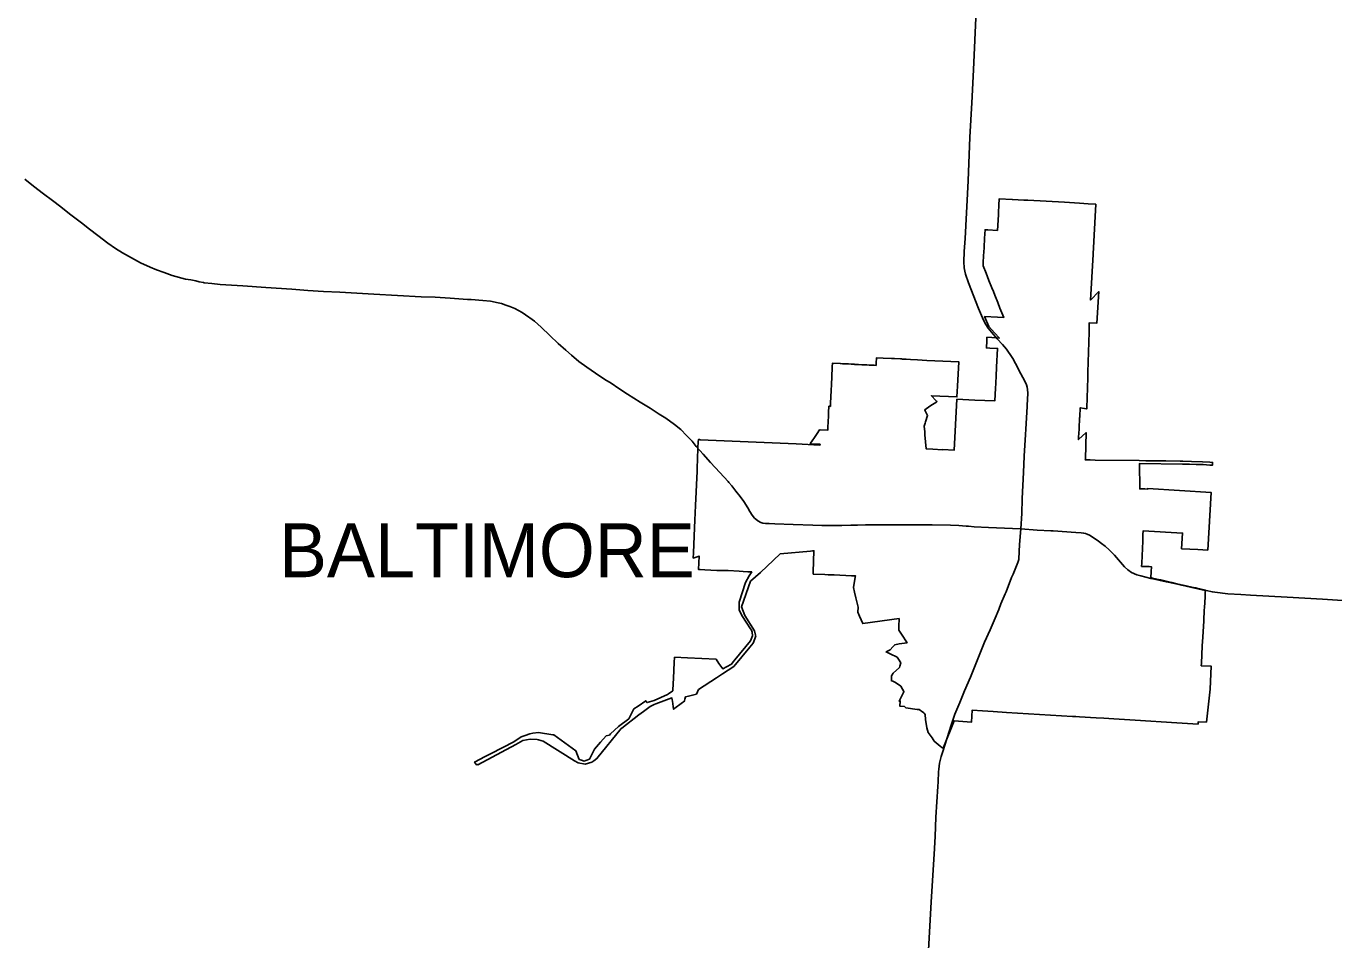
# Model space of a CAD drawing. Extents: x 1801177 to 2073177, y 551183 to 727183.
# Drawn here: x 1919316 to 1946535, y 663604 to 682611 of the extents above; entities that cross this region are included whole.
import ezdxf

# ---------------------------------------------------------------- set-up
doc = ezdxf.new("R2010")
doc.units = 0
for name, color, linetype in [('GM_X_Corporation', 7, 'Continuous'), ('GM_X_Corporation_Text', 7, 'Continuous'), ('GM_X_State_Route', 7, 'Continuous')]:
    doc.layers.add(name, color=color, linetype=linetype)

msp = doc.modelspace()

# ---------------------------------------------------------------- linework, layer by layer
at = {"layer": 'GM_X_Corporation'}
msp.add_lwpolyline([(1941583, 678909), (1941525, 677874), (1941524, 677860), (1941471, 676912), (1941643, 677090), (1941604, 676433), (1941444, 676441), (1941443, 676398), (1941439, 676247), (1941415, 675413), (1941413, 675297), (1941393, 674669), (1941392, 674649), (1941344, 674658), (1941255, 674674), (1941252, 674608), (1941249, 674554), (1941245, 674476), (1941244, 674460), (1941239, 674376), (1941237, 674328), (1941234, 674275), (1941233, 674262), (1941233, 674250), (1941232, 674236), (1941227, 674136), (1941227, 674130), (1941223, 674072), (1941221, 674027), (1941221, 674023), (1941220, 674011), (1941379, 674156), (1941363, 673613), (1941362, 673589), (1941465, 673587), (1941569, 673583), (1942485, 673573), (1942623, 673571), (1943036, 673566), (1943336, 673562), (1943390, 673562), (1943573, 673558), (1943798, 673549), (1943957, 673541), (1944012, 673537), (1944009, 673478), (1943954, 673481), (1943812, 673489), (1943670, 673495), (1943528, 673499), (1943386, 673502), (1942488, 673513), (1942496, 672986), (1942603, 672983), (1942659, 672981), (1942660, 672993), (1943983, 672909), (1943911, 671712), (1943705, 671722), (1943535, 671730), (1943366, 671739), (1943387, 672066), (1942565, 672112), (1942562, 672034), (1942559, 671968), (1942556, 671899), (1942537, 671440), (1942537, 671439), (1942534, 671373), (1942667, 671369), (1942689, 671368), (1942737, 671366), (1942733, 671263), (1942729, 671138), (1942741, 671135), (1942758, 671131), (1942762, 671130), (1942888, 671100), (1942932, 671090), (1943046, 671062), (1943103, 671049), (1943160, 671035), (1943318, 670998), (1943324, 670996), (1943326, 670996), (1943331, 670995), (1943348, 670990), (1943370, 670985), (1943399, 670979), (1943489, 670960), (1943643, 670928), (1943660, 670924), (1943680, 670919), (1943862, 670877), (1943860, 670836), (1943854, 670741), (1943841, 670509), (1943839, 670468), (1943826, 670238), (1943808, 669903), (1943797, 669718), (1943778, 669353), (1943775, 669307), (1943984, 669296), (1943958, 668816), (1943883, 668134), (1943712, 668142), (1943708, 668092), (1943269, 668119), (1942401, 668173), (1941956, 668200), (1941748, 668213), (1941590, 668223), (1941244, 668244), (1941167, 668249), (1941094, 668253), (1939722, 668336), (1939443, 668353), (1939222, 668369), (1939010, 668385), (1938994, 668135), (1938629, 668163), (1938400, 667594), (1938400, 667593), (1938373, 667603), (1938338, 667633), (1938338, 667633), (1938217, 667737), (1938171, 667803), (1938093, 667916), (1938063, 668011), (1938038, 668185), (1938026, 668291), (1938007, 668319), (1938002, 668326), (1937996, 668330), (1937983, 668339), (1937901, 668393), (1937879, 668396), (1937859, 668399), (1937629, 668430), (1937629, 668430), (1937615, 668442), (1937595, 668459), (1937504, 668463), (1937509, 668571), (1937499, 668572), (1937484, 668572), (1937528, 668654), (1937586, 668763), (1937583, 668769), (1937556, 668819), (1937552, 668829), (1937526, 668876), (1937524, 668880), (1937408, 668956), (1937370, 668975), (1937324, 668999), (1937325, 669012), (1937326, 669038), (1937329, 669098), (1937365, 669153), (1937491, 669270), (1937500, 669300), (1937523, 669369), (1937473, 669444), (1937445, 669486), (1937299, 669553), (1937284, 669560), (1937216, 669592), (1937298, 669640), (1937353, 669698), (1937395, 669741), (1937484, 669759), (1937651, 669784), (1937536, 669960), (1937480, 670047), (1937482, 670123), (1937486, 670287), (1936730, 670184), (1936730, 670184), (1936663, 670338), (1936627, 670420), (1936634, 670523), (1936614, 670608), (1936588, 670718), (1936557, 670839), (1936534, 670931), (1936575, 671146), (1936580, 671176), (1936492, 671179), (1936131, 671194), (1936008, 671199), (1935937, 671202), (1935700, 671211), (1935698, 671211), (1935699, 671261), (1935713, 671697), (1935683, 671694), (1935642, 671690), (1935009, 671632), (1934869, 671501), (1934603, 671249), (1934395, 671064), (1934209, 670531), (1934272, 670351), (1934475, 670035), (1934499, 669940), (1934502, 669928), (1934480, 669866), (1934447, 669775), (1934377, 669691), (1934046, 669291), (1933812, 669138), (1933807, 669135), (1933688, 669057), (1933314, 668811), (1933267, 668717), (1933267, 668717), (1933104, 668675), (1933040, 668659), (1933039, 668659), (1933027, 668614), (1933019, 668584), (1933019, 668569), (1932980, 668540), (1932792, 668402), (1932792, 668402), (1932768, 668568), (1932764, 668596), (1932757, 668638), (1932757, 668638), (1932423, 668516), (1932385, 668498), (1932306, 668459), (1932166, 668355), (1932071, 668284), (1931712, 668009), (1931700, 668000), (1931195, 667373), (1931130, 667327), (1931090, 667299), (1930949, 667262), (1930806, 667283), (1930806, 667283), (1930728, 667331), (1930078, 667736), (1929980, 667765), (1929950, 667774), (1929808, 667780), (1929657, 667749), (1929507, 667665), (1928715, 667245), (1928715, 667245), (1928711, 667252), (1928710, 667254), (1928710, 667254), (1928697, 667246), (1928691, 667243), (1928650, 667303), (1928870, 667418), (1928993, 667483), (1929468, 667725), (1929621, 667829), (1929706, 667858), (1929797, 667889), (1929865, 667900), (1929979, 667918), (1930278, 667870), (1930295, 667867), (1930302, 667866), (1930302, 667866), (1930757, 667539), (1930829, 667357), (1930872, 667343), (1930931, 667324), (1930968, 667337), (1931040, 667362), (1931147, 667571), (1931273, 667713), (1931389, 667845), (1931452, 667861), (1931455, 667862), (1931455, 667862), (1931482, 667888), (1931482, 667888), (1931644, 668042), (1931858, 668203), (1931966, 668408), (1932053, 668468), (1932053, 668468), (1932213, 668579), (1932213, 668579), (1932236, 668549), (1932242, 668541), (1932242, 668540), (1932390, 668581), (1932667, 668707), (1932688, 668723), (1932773, 668786), (1932774, 668800), (1932774, 668807), (1932788, 669047), (1932788, 669047), (1932806, 669375), (1932812, 669481), (1932812, 669481), (1933083, 669469), (1933083, 669469), (1933677, 669441), (1933737, 669356), (1933817, 669242), (1933817, 669242), (1933892, 669283), (1933994, 669340), (1934035, 669388), (1934070, 669429), (1934392, 669821), (1934433, 669929), (1934425, 670001), (1934422, 670028), (1934412, 670044), (1934391, 670075), (1934224, 670333), (1934180, 670418), (1934155, 670467), (1934155, 670585), (1934156, 670626), (1934292, 671038), (1934365, 671179), (1934419, 671257), (1934339, 671262), (1934242, 671268), (1934156, 671274), (1933931, 671289), (1933821, 671289), (1933692, 671289), (1933440, 671301), (1933347, 671306), (1933314, 671307), (1933321, 671588), (1933202, 671545), (1933208, 671658), (1933230, 672174), (1933236, 672331), (1933249, 672641), (1933280, 673352), (1933282, 673412), (1933300, 673823), (1933300, 673837), (1933306, 673963), (1933308, 674010), (1933333, 674009), (1933347, 674008), (1935343, 673919), (1935839, 673897), (1935840, 673912), (1935635, 673922), (1935642, 673933), (1935678, 673985), (1935724, 674054), (1935782, 674139), (1935832, 674212), (1935844, 674211), (1936000, 674204), (1936000, 674207), (1936002, 674243), (1936005, 674308), (1936007, 674341), (1936008, 674367), (1936010, 674408), (1936014, 674476), (1936015, 674499), (1936016, 674523), (1936019, 674576), (1936025, 674704), (1936042, 674703), (1936055, 674702), (1936059, 674780), (1936061, 674810), (1936063, 674858), (1936067, 674936), (1936070, 675000), (1936070, 675015), (1936078, 675172), (1936084, 675302), (1936089, 675392), (1936091, 675442), (1936095, 675522), (1936099, 675599), (1936257, 675591), (1936258, 675591), (1936264, 675591), (1936306, 675589), (1936339, 675587), (1936413, 675584), (1936433, 675583), (1936488, 675580), (1936508, 675579), (1936541, 675577), (1936551, 675577), (1936563, 675576), (1936611, 675574), (1936638, 675572), (1936713, 675569), (1936723, 675568), (1936788, 675565), (1936817, 675563), (1936863, 675561), (1936938, 675557), (1936969, 675556), (1937007, 675554), (1937011, 675638), (1937014, 675679), (1937016, 675713), (1937157, 675706), (1937330, 675697), (1937379, 675695), (1937390, 675694), (1937518, 675687), (1937535, 675687), (1937557, 675685), (1937633, 675682), (1937723, 675677), (1937869, 675669), (1938062, 675659), (1938730, 675625), (1938703, 675119), (1938691, 674898), (1938159, 674923), (1938250, 674823), (1938262, 674810), (1938272, 674799), (1938128, 674703), (1938021, 674631), (1938032, 674608), (1938079, 674512), (1938039, 674383), (1938029, 674350), (1938010, 674289), (1938020, 674175), (1938021, 674158), (1938025, 674112), (1938051, 673815), (1938051, 673815), (1938191, 673809), (1938392, 673800), (1938392, 673803), (1938634, 673792), (1938689, 674850), (1939060, 674834), (1939477, 674815), (1939492, 675081), (1939497, 675178), (1939506, 675341), (1939515, 675500), (1939515, 675514), (1939537, 675908), (1939533, 675908), (1939378, 675915), (1939304, 675919), (1939310, 676065), (1939314, 676138), (1939519, 676129), (1939573, 676123), (1939474, 676233), (1939357, 676364), (1939266, 676569), (1939535, 676555), (1939665, 676548), (1939664, 676549), (1939585, 676747), (1939539, 676863), (1939478, 677015), (1939448, 677091), (1939417, 677167), (1939356, 677320), (1939295, 677472), (1939235, 677624), (1939238, 677693), (1939246, 677832), (1939255, 677998), (1939256, 678014), (1939266, 678196), (1939271, 678290), (1939276, 678377), (1939331, 678374), (1939532, 678362), (1939538, 678463), (1939552, 678691), (1939557, 678796), (1939559, 678822), (1939562, 678888), (1939569, 679021), (1939841, 679006), (1939843, 679006), (1940082, 678993), (1940165, 678988), (1940928, 678946), (1941239, 678928), (1941419, 678918)], close=True, dxfattribs=at)
at = {"layer": 'GM_X_State_Route'}
for points in [[(1939492, 676148), (1939406, 676244), (1939340, 676330), (1939289, 676408), (1939246, 676492), (1939142, 676736), (1938933, 677271), (1938870, 677451), (1938852, 677514), (1938840, 677582), (1938834, 677708), (1938843, 677924), (1938864, 678192), (1938923, 679394), (1938958, 680299), (1938997, 681014), (1939037, 681705), (1939091, 682939), (1939200, 684979), (1939238, 685711), (1939301, 687028), (1939518, 691039), (1939570, 692226), (1939577, 692277)], [(1919291, 679425), (1919469, 679285), (1919680, 679125), (1919862, 678984), (1920037, 678850), (1920221, 678705), (1920471, 678517), (1920634, 678390), (1920806, 678253), (1921013, 678098), (1921172, 677989), (1921319, 677897), (1921506, 677788), (1921696, 677690), (1921897, 677598), (1922031, 677540), (1922187, 677485), (1922358, 677427), (1922633, 677351), (1922744, 677333), (1922850, 677310)], [(1922850, 677310), (1922918, 677295), (1923006, 677276)], [(1923006, 677276), (1923021, 677273), (1923184, 677255), (1923354, 677239), (1923829, 677206), (1924306, 677171), (1924844, 677137), (1925181, 677114), (1925506, 677092), (1925842, 677078), (1926553, 677036), (1927541, 676981), (1927829, 676970), (1928142, 676949), (1928503, 676927), (1928580, 676922)], [(1928580, 676922), (1928822, 676907), (1928978, 676889), (1929138, 676858), (1929210, 676840), (1929303, 676809), (1929386, 676777), (1929489, 676739), (1929638, 676652), (1929779, 676559), (1929801, 676543)], [(1929801, 676543), (1929899, 676474), (1930037, 676351), (1930216, 676179), (1930390, 676012), (1930548, 675869), (1930664, 675765), (1930823, 675637), (1930983, 675515), (1931166, 675390), (1931363, 675262), (1931493, 675181), (1931654, 675075), (1931833, 674955), (1932099, 674790), (1932304, 674662), (1932489, 674542), (1932628, 674455), (1932808, 674327), (1932940, 674223), (1933060, 674096), (1933176, 673975), (1933259, 673870), (1933338, 673784)], [(1940155, 674718), (1940166, 674979), (1940158, 675054), (1940149, 675102), (1940135, 675152), (1940101, 675227), (1940023, 675378), (1939912, 675591), (1939853, 675696), (1939841, 675719), (1939719, 675892), (1939638, 675989), (1939529, 676105), (1939492, 676148)], [(1940049, 672781), (1940049, 672787), (1940073, 673326), (1940089, 673665), (1940090, 673672), (1940111, 674000), (1940132, 674346), (1940154, 674697), (1940155, 674718)], [(1933338, 673784), (1933406, 673710), (1933562, 673536), (1933754, 673324), (1933928, 673139), (1933944, 673119)], [(1933944, 673119), (1934003, 673047), (1934086, 672940), (1934176, 672825), (1934252, 672721), (1934339, 672588), (1934378, 672518), (1934430, 672440), (1934477, 672376), (1934506, 672352)], [(1940021, 672154), (1940040, 672474), (1940049, 672781)], [(1934506, 672352), (1934546, 672318), (1934610, 672289), (1934653, 672275), (1934710, 672264), (1934783, 672262), (1934901, 672259), (1935281, 672245), (1935688, 672230), (1935881, 672222), (1936071, 672224), (1936293, 672226), (1936479, 672227), (1936617, 672231)], [(1936617, 672231), (1936786, 672235), (1937013, 672236), (1937258, 672238), (1937289, 672238)], [(1937289, 672238), (1937474, 672234), (1937703, 672234), (1937964, 672237), (1938177, 672240), (1938556, 672230), (1938730, 672220), (1938885, 672210)], [(1938885, 672210), (1938931, 672207), (1939052, 672196), (1939349, 672180)], [(1939349, 672180), (1939682, 672166), (1939849, 672159), (1940021, 672154)], [(1939975, 671531), (1939994, 671831), (1940021, 672154)], [(1940021, 672154), (1940361, 672128), (1940642, 672112)], [(1940642, 672112), (1940694, 672109), (1941167, 672080), (1941273, 672072), (1941327, 672066), (1941364, 672054), (1941401, 672040), (1941447, 672019), (1941502, 671985), (1941634, 671897), (1941701, 671849), (1941777, 671792), (1941862, 671719), (1941969, 671606), (1942181, 671366), (1942250, 671298), (1942322, 671247), (1942434, 671197), (1942519, 671173), (1942726, 671123), (1942741, 671119)], [(1939829, 671141), (1939857, 671213), (1939958, 671454), (1939975, 671515), (1939975, 671531)], [(1939694, 670803), (1939712, 670846), (1939829, 671141)], [(1942741, 671119), (1943043, 671054), (1943053, 671052)], [(1943053, 671052), (1943153, 671029), (1943158, 671028), (1943859, 670872), (1943880, 670868)], [(1938691, 668399), (1938750, 668539), (1938846, 668781), (1938969, 669067), (1939267, 669795), (1939381, 670055), (1939487, 670299), (1939559, 670479), (1939605, 670592), (1939694, 670803)], [(1943880, 670868), (1944009, 670841), (1944056, 670834), (1944329, 670804), (1944601, 670789), (1944799, 670776), (1945565, 670732), (1946298, 670688), (1947032, 670645), (1947352, 670626), (1947788, 670600), (1948816, 670538), (1949262, 670516)], [(1938360, 667415), (1938398, 667524), (1938567, 668067), (1938648, 668299), (1938691, 668399)], [(1938292, 666793), (1938298, 666891), (1938307, 667097), (1938314, 667158)], [(1938314, 667158), (1938328, 667277), (1938360, 667415)], [(1937995, 661278), (1938024, 661661), (1938046, 662371), (1938087, 663139), (1938153, 664397), (1938215, 665389), (1938236, 665755), (1938252, 666159), (1938292, 666793)]]:
    msp.add_lwpolyline(points, dxfattribs=at)

# ---------------------------------------------------------------- texts
at = {"layer": 'GM_X_Corporation_Text'}
msp.add_text('BALTIMORE', height=1120, rotation=0, dxfattribs=at).set_placement((1924578, 671148))

doc.saveas('drawing.dxf')
